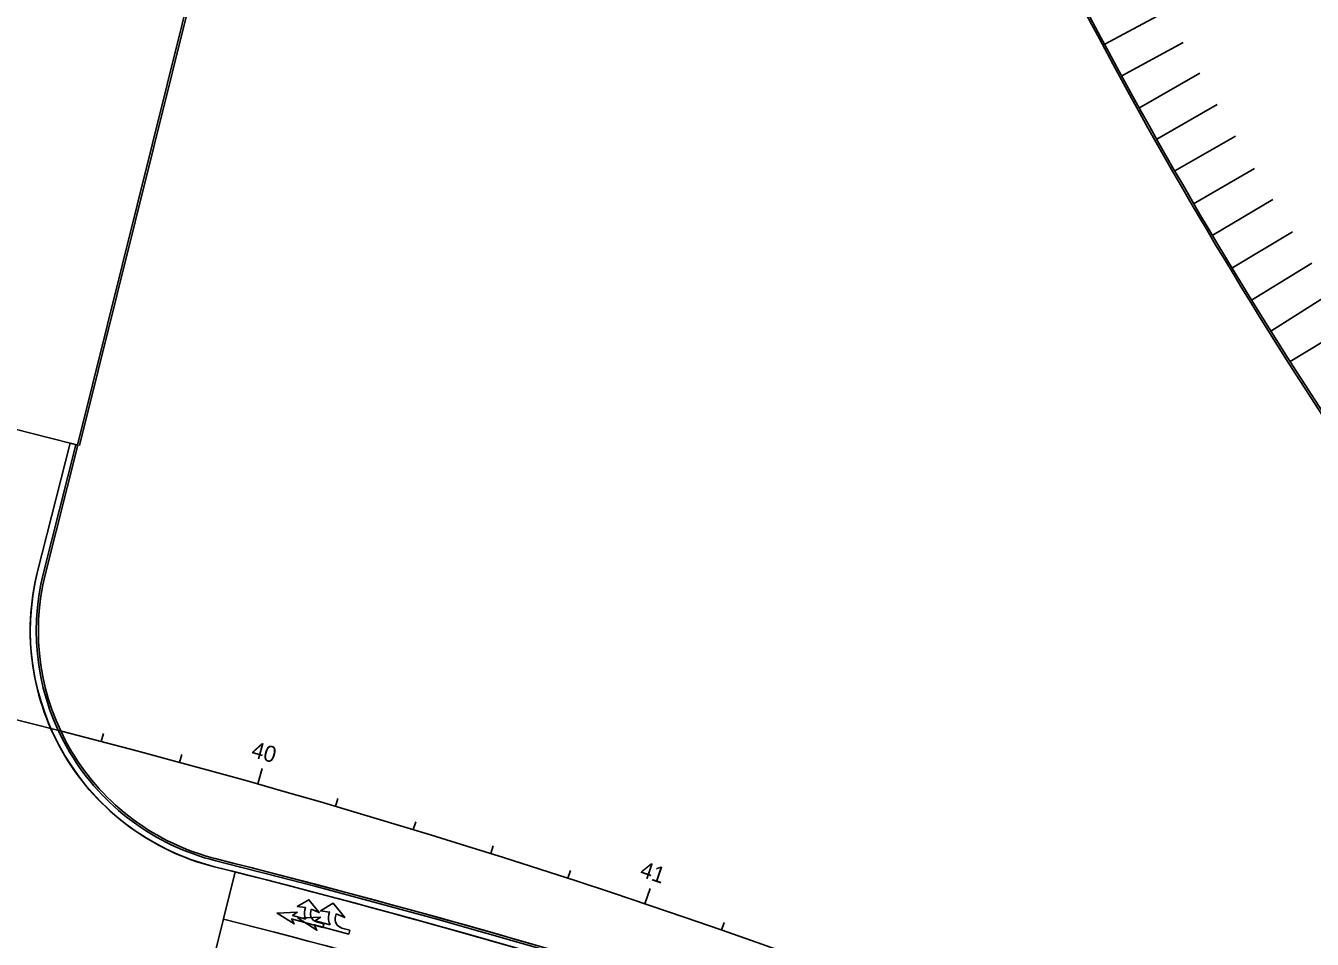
# Model space of a CAD drawing. Extents: x 468143 to 491361, y 1438528 to 1468730.
# Drawn here: x 487025 to 487342.4, y 1467474 to 1467699.5 of the extents above; entities that cross this region are included whole.
import ezdxf

# ---------------------------------------------------------------- set-up
doc = ezdxf.new("R2010")
doc.units = 0
doc.layers.add('Default', color=7, linetype='Continuous')
doc.layers.add('Xreference_dp', color=7, linetype='Continuous')

# ---------------------------------------------------------------- blocks, each defined once
blk = doc.blocks.new('DARightThru')
at = {"layer": 'Default'}
for points in [[(5.05, 2.17), (8.83, 2.17), (7.83, 1), (13.08, 2.67), (7.83, 4.33), (8.83, 3.17), (0, 3.17), (0, 2.17), (2, 2.17)], [(4.33, -0.83), (2, -0.5), (5.67, -3.17), (8.25, -0.5), (6, -0.83), (6, -0.17)], [(4.33, -0.17), (4.33, -0.83)]]:
    blk.add_lwpolyline(points, dxfattribs=at)
for centre, radius, start, end in [((2, -0.17), 2.33, 360, 90), ((2.67, -0.17), 3.33, 0, 44.427)]:
    blk.add_arc(centre, radius, start, end, dxfattribs=at)
blk = doc.blocks.new('DARightThru_1')
at = {"layer": 'Default'}
for points in [[(5.05, 2.17), (8.83, 2.17), (7.83, 1), (13.08, 2.67), (7.83, 4.33), (8.83, 3.17), (0, 3.17), (0, 2.17), (2, 2.17)], [(4.33, -0.83), (2, -0.5), (5.67, -3.17), (8.25, -0.5), (6, -0.83), (6, -0.17)], [(4.33, -0.17), (4.33, -0.83)]]:
    blk.add_lwpolyline(points, dxfattribs=at)
for centre, radius, start, end in [((2, -0.17), 2.33, 360, 90), ((2.67, -0.17), 3.33, 0, 44.427)]:
    blk.add_arc(centre, radius, start, end, dxfattribs=at)
blk = doc.blocks.new('DARightThru_2_1')
at = {"layer": 'Default'}
for points in [[(5.05, 2.17), (8.83, 2.17), (7.83, 1), (13.08, 2.67), (7.83, 4.33), (8.83, 3.17), (0, 3.17), (0, 2.17), (2, 2.17)], [(4.33, -0.83), (2, -0.5), (5.67, -3.17), (8.25, -0.5), (6, -0.83), (6, -0.17)], [(4.33, -0.17), (4.33, -0.83)]]:
    blk.add_lwpolyline(points, dxfattribs=at)
for centre, radius, start, end in [((2, -0.17), 2.33, 360, 90), ((2.67, -0.17), 3.33, 0, 44.427)]:
    blk.add_arc(centre, radius, start, end, dxfattribs=at)

msp = doc.modelspace()

# ---------------------------------------------------------------- linework, layer by layer
at = {"layer": 'Xreference_dp'}
for p, q in [((487123.16, 1467937.41), (487038.31, 1467595.84)), ((487306.49, 1467703.07), (487291.27, 1467694.89)), ((487310.61, 1467695.29), (487295.44, 1467687.13)), ((487314.69, 1467687.72), (487299.69, 1467679.14)), ((487319.01, 1467680.06), (487304.06, 1467671.5)), ((487323.52, 1467672.21), (487308.51, 1467663.66)), ((487328.17, 1467664.25), (487313.18, 1467655.53)), ((487332.72, 1467656.61), (487317.77, 1467647.73)), ((487337.55, 1467648.64), (487322.64, 1467639.61)), ((487342.32, 1467640.9), (487327.47, 1467631.72)), ((487347, 1467633.43), (487332.23, 1467624.11)), ((487351.97, 1467625.65), (487337.02, 1467616.59)), ((487035.98, 1467596.43), (487012.71, 1467602.31)), ((487027.98, 1467564.8), (487035.98, 1467596.43)), ((487027.98, 1467564.8), (487035.98, 1467596.43)), ((487027.98, 1467564.8), (487035.98, 1467596.43)), ((487029.44, 1467564.43), (487037.43, 1467596.06)), ((487029.92, 1467564.31), (487037.91, 1467595.94)), ((487035.98, 1467596.43), (487037.91, 1467595.94)), ((487043.68, 1467522.81), (487044.19, 1467524.75)), ((487063.01, 1467517.66), (487063.53, 1467519.59)), ((487082.28, 1467512.32), (487083.37, 1467516.17)), ((487101.5, 1467506.79), (487102.06, 1467508.71)), ((487120.66, 1467501.06), (487121.25, 1467502.98)), ((487139.77, 1467495.15), (487140.37, 1467497.05)), ((487076.74, 1467490.6), (487062.17, 1467432.39)), ((487158.81, 1467489.04), (487159.43, 1467490.94)), ((487177.8, 1467482.74), (487179.07, 1467486.53)), ((487196.71, 1467476.25), (487197.37, 1467478.14))]:
    msp.add_line(p, q, dxfattribs=at)
msp.add_lwpolyline([(487122.67, 1467937.53), (487037.82, 1467595.96)], dxfattribs=at)
for centre, radius, start, end in [((488343.26, 1468257.64), 1193.62, 203.85451, 216.66135), ((488343.26, 1468257.64), 1193.12, 203.85451, 216.63757), ((488517.96, 1468387.25), 1345.98, 207.08377, 216.1793), ((486537.7, 1465584.94), 2002.84, 65.37329, 99.90546), ((487086.15, 1467550.1), 60, 165.8192, 255.9413), ((487086.33, 1467550.21), 60.15, 165.9597, 255.5119), ((487086.15, 1467550.1), 58.5, 165.8192, 255.9413), ((487086.15, 1467550.1), 58, 165.8192, 255.9413), ((487129.34, 1467501.5), 150, 166.3971, 245.8239), ((486541.29, 1465374.28), 2185, 72.14502, 75.94924), ((486541.29, 1465374.28), 2185, 65.36901, 75.94924), ((486541.29, 1465374.28), 2183, 72.14397, 75.94924), ((486541.29, 1465374.28), 2183, 65.36658, 75.94131), ((486541.29, 1465374.28), 2184.5, 65.36842, 75.94131), ((486541.29, 1465374.28), 2171, 72.15323, 75.80077), ((486541.29, 1465374.28), 2100, 65.36712, 99.90595)]:
    msp.add_arc(centre, radius, start, end, dxfattribs=at)

# ---------------------------------------------------------------- block references
at = {"layer": 'Xreference_dp', "xscale": 0.9000000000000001, "yscale": 0.8999999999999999, "rotation": 164.77259329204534}
for name in ['DARightThru_1', 'DARightThru_2_1']:
    msp.add_blockref(name, (487099.06, 1467479.67), dxfattribs=at)
at = {"layer": 'Xreference_dp', "rotation": 164.77259329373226}
msp.add_blockref('DARightThru', (487105.56, 1467478.33), dxfattribs=at)

# ---------------------------------------------------------------- texts
at = {"layer": 'Xreference_dp'}
for s, rotation, p in [('40', 344.2224, (487080.46, 1467519.07)), ('41', 341.3617, (487176.31, 1467489.57))]:
    msp.add_text(s, height=4, rotation=rotation, dxfattribs=at).set_placement(p)

doc.saveas('drawing.dxf')
